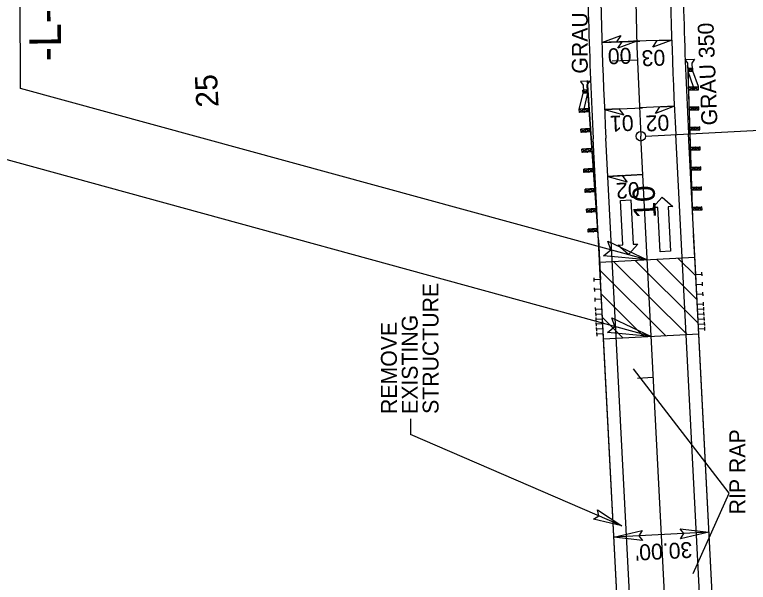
# Model space of a CAD drawing. Extents: x 1373164 to 1374172, y 550391 to 553180.
# Drawn here: x 1373510 to 1373740.9, y 551698 to 551876.6 of the extents above; entities that cross this region are included whole.
import ezdxf

# ---------------------------------------------------------------- set-up
doc = ezdxf.new("R2010")
doc.units = 0
for name, color, linetype in [('Default', 7, 'Continuous'), ('Default Symbol Cogo Elevation', 7, 'Continuous'), ('Exist Building Cogo Elevation', 7, 'Continuous'), ('Exist Building Cogo Number', 7, 'Continuous'), ('Exist Building Cogo Point CELL', 7, 'Continuous'), ('Exist Other Culture Fence Line Cogo Comment', 7, 'Continuous'), ('Exist Other Culture Fence Line Cogo Elevation', 7, 'Continuous'), ('Exist Other Culture Fence Line Cogo Point CELL', 7, 'Continuous'), ('Exist Other Culture Gate Cogo Comment', 7, 'Continuous'), ('Exist Other Culture Gate Cogo Elevation', 7, 'Continuous'), ('Exist Other Culture Gate Cogo Number', 7, 'Continuous'), ('Exist Other Culture Gate Cogo Point CELL', 7, 'Continuous'), ('Exist Roads EOP Other Cogo Elevation', 7, 'Continuous'), ('Exist Structure Major Deck Tunnel Box Culvert Cogo Point CELL', 7, 'Continuous'), ('Exist Structure Minor Pipes RCP 18 Inch Cogo Comment', 7, 'Continuous'), ('Exist Structure Minor Pipes RCP 18 Inch Cogo Elevation', 7, 'Continuous'), ('Exist Structure Minor Pipes RCP 18 Inch Cogo Number', 7, 'Continuous'), ('Exist Utilities Sanitary Sewer Manhole Cogo Elevation', 7, 'Continuous'), ('Exist Utilities Sanitary Sewer Manhole Cogo Number', 7, 'Continuous')]:
    doc.layers.add(name, color=color, linetype=linetype)

msp = doc.modelspace()

# ---------------------------------------------------------------- linework, layer by layer
at = {"layer": 'Default Symbol Cogo Elevation'}
for p, q in [((1373730.5, 551597.19), (1373718.01, 551838.94)), ((1373711.58, 551537.14), (1373696.04, 551837.8))]:
    msp.add_line(p, q, dxfattribs=at)
for radius in [1546, 1524]:
    msp.add_arc((1375239.98, 551917.59), radius, 178.33248, 182.95848, dxfattribs=at)
at = {"layer": 'Exist Building Cogo Elevation'}
for p, q in [((1373723.38, 551812.55), (1373721.87, 551861.36)), ((1373693.69, 551805.82), (1373690.24, 551855.95)), ((1373724.29, 551794.89), (1373723.65, 551807.37)), ((1373694.33, 551793.34), (1373693.69, 551805.82)), ((1373725.26, 551776.16), (1373724.29, 551794.89)), ((1373695.3, 551774.61), (1373694.33, 551793.34))]:
    msp.add_line(p, q, dxfattribs=at)
at = {"layer": 'Exist Building Cogo Number'}
for p, q in [((1373735.61, 551575.89), (1373722, 551839.14)), ((1373710.16, 551487), (1373692.04, 551837.6))]:
    msp.add_line(p, q, dxfattribs=at)
for radius in [1550, 1520]:
    msp.add_arc((1375239.98, 551917.59), radius, 180.19879, 182.95848, dxfattribs=at)
at = {"layer": 'Exist Building Cogo Point CELL'}
msp.add_line((1373710.95, 551762.41), (1373705.96, 551762.15), dxfattribs=at)
at = {"layer": 'Exist Other Culture Fence Line Cogo Comment'}
for p, q in [((1373694.05, 551798.75), (1373724.01, 551800.3)), ((1373721.59, 551775.97), (1373698.45, 551798.98)), ((1373725.08, 551779.55), (1373705.19, 551799.33)), ((1373724.7, 551786.98), (1373711.93, 551799.68)), ((1373724.32, 551794.41), (1373718.67, 551800.02)), ((1373725.26, 551776.16), (1373724.01, 551800.3)), ((1373695.3, 551774.61), (1373694.05, 551798.75)), ((1373714.85, 551775.62), (1373694.19, 551796.17)), ((1373708.11, 551775.28), (1373694.57, 551788.74)), ((1373701.37, 551774.93), (1373694.95, 551781.31))]:
    msp.add_line(p, q, dxfattribs=at)
at = {"layer": 'Exist Other Culture Fence Line Cogo Elevation'}
for p, q in [((1373695.3, 551774.61), (1373725.26, 551776.16)), ((1373731.61, 551653.33), (1373725.26, 551776.16)), ((1373701.65, 551651.78), (1373695.3, 551774.61))]:
    msp.add_line(p, q, dxfattribs=at)
at = {"layer": 'Exist Other Culture Fence Line Cogo Point CELL'}
for p, q in [((1373694.78, 551867.92), (1373706.77, 551868.31)), ((1373705.77, 551868.28), (1373694.78, 551867.92)), ((1373716.77, 551868.63), (1373704.77, 551868.25)), ((1373717.58, 551847.8), (1373706.59, 551847.29)), ((1373717.58, 551847.8), (1373706.59, 551847.29)), ((1373695.6, 551846.79), (1373707.59, 551847.34)), ((1373707.65, 551826.32), (1373696.66, 551825.75)), ((1373696.66, 551825.75), (1373707.65, 551826.32))]:
    msp.add_line(p, q, dxfattribs=at)
for points in [[(1373694.78, 551867.92), (1373700.71, 551870.12), (1373699.4, 551868.07)], [(1373705.77, 551868.28), (1373699.84, 551866.09), (1373701.15, 551868.13)], [(1373716.77, 551868.63), (1373710.83, 551866.44), (1373712.14, 551868.48)], [(1373717.58, 551847.8), (1373711.68, 551845.52), (1373712.96, 551847.59)], [(1373695.6, 551846.79), (1373701.69, 551845.07), (1373700.22, 551847)], [(1373696.66, 551825.75), (1373702.76, 551824.07), (1373701.28, 551825.99)]]:
    msp.add_lwpolyline(points, close=True, dxfattribs=at)
at = {"layer": 'Exist Other Culture Gate Cogo Comment'}
for p, q in [((1373720.95, 551862.49), (1373723.89, 551862.64)), ((1373721.87, 551861.36), (1373720.95, 551862.49)), ((1373721.97, 551859.31), (1373721.87, 551861.36)), ((1373723.89, 551862.64), (1373723.09, 551861.42)), ((1373723.09, 551861.42), (1373723.2, 551859.37)), ((1373721.88, 551859.78), (1373723.38, 551859.83)), ((1373721.88, 551859.78), (1373723.42, 551858.83)), ((1373723.38, 551812.55), (1373721.9, 551859.28)), ((1373723.38, 551859.83), (1373721.92, 551858.78)), ((1373722.58, 551859.34), (1373721.97, 551859.31)), ((1373723.2, 551859.37), (1373722.58, 551859.34)), ((1373723.42, 551858.83), (1373723.38, 551859.83)), ((1373723.42, 551858.83), (1373723.4, 551859.33)), ((1373721.92, 551858.78), (1373723.42, 551858.83)), ((1373723.6, 551853.93), (1373721.92, 551858.78)), ((1373725.13, 551853.98), (1373723.42, 551858.83)), ((1373690.95, 551855.74), (1373688.01, 551855.59)), ((1373688.01, 551855.59), (1373688.93, 551854.46)), ((1373688.93, 551854.46), (1373689.04, 551852.41)), ((1373690.15, 551854.52), (1373690.95, 551855.74)), ((1373690.26, 551852.48), (1373690.15, 551854.52)), ((1373690.31, 551852.95), (1373688.81, 551852.85)), ((1373688.88, 551851.85), (1373688.81, 551852.85)), ((1373688.81, 551852.85), (1373690.38, 551851.95)), ((1373688.88, 551851.85), (1373688.84, 551852.35)), ((1373690.31, 551852.95), (1373688.88, 551851.85)), ((1373689.04, 551852.41), (1373689.65, 551852.45)), ((1373689.65, 551852.45), (1373690.26, 551852.48)), ((1373693.69, 551805.82), (1373690.34, 551852.45)), ((1373722.07, 551853.88), (1373725.13, 551853.98)), ((1373723.63, 551852.93), (1373722.07, 551853.88)), ((1373722.1, 551852.88), (1373723.6, 551853.93)), ((1373722.1, 551852.88), (1373725.16, 551852.98)), ((1373723.63, 551852.93), (1373723.6, 551853.93)), ((1373723.6, 551853.93), (1373725.16, 551852.98)), ((1373725.13, 551853.98), (1373723.63, 551852.93)), ((1373725.16, 551852.98), (1373725.13, 551853.98)), ((1373687.67, 551846.85), (1373688.88, 551851.85)), ((1373690.38, 551851.95), (1373688.88, 551851.85)), ((1373689.2, 551846.96), (1373690.38, 551851.95)), ((1373722.27, 551847.58), (1373725.27, 551847.68)), ((1373723.8, 551846.63), (1373722.27, 551847.58)), ((1373722.3, 551846.58), (1373723.77, 551847.63)), ((1373723.8, 551846.63), (1373723.77, 551847.63)), ((1373723.77, 551847.63), (1373725.3, 551846.68)), ((1373725.27, 551847.68), (1373723.8, 551846.63)), ((1373725.3, 551846.68), (1373725.27, 551847.68)), ((1373690.73, 551847.07), (1373687.67, 551846.85)), ((1373687.74, 551845.85), (1373687.67, 551846.85)), ((1373687.67, 551846.85), (1373689.27, 551845.96)), ((1373689.2, 551846.96), (1373687.74, 551845.85)), ((1373690.8, 551846.07), (1373687.74, 551845.85)), ((1373689.27, 551845.96), (1373689.2, 551846.96)), ((1373690.8, 551846.07), (1373689.2, 551846.96)), ((1373689.27, 551845.96), (1373690.73, 551847.07)), ((1373722.3, 551846.58), (1373725.3, 551846.68)), ((1373691.18, 551840.78), (1373688.19, 551840.57)), ((1373688.26, 551839.57), (1373688.19, 551840.57)), ((1373688.19, 551840.57), (1373689.75, 551839.68)), ((1373689.68, 551840.67), (1373688.26, 551839.57)), ((1373689.75, 551839.68), (1373689.68, 551840.67)), ((1373691.25, 551839.78), (1373689.68, 551840.67)), ((1373689.75, 551839.68), (1373691.18, 551840.78)), ((1373722.47, 551841.28), (1373725.61, 551841.38)), ((1373724.07, 551840.33), (1373722.47, 551841.28)), ((1373722.5, 551840.28), (1373724.04, 551841.33)), ((1373724.07, 551840.33), (1373724.04, 551841.33)), ((1373724.04, 551841.33), (1373725.64, 551840.38)), ((1373725.61, 551841.38), (1373724.07, 551840.33)), ((1373725.64, 551840.38), (1373725.61, 551841.38)), ((1373691.25, 551839.78), (1373688.26, 551839.57)), ((1373722.5, 551840.28), (1373725.64, 551840.38)), ((1373691.63, 551834.5), (1373688.5, 551834.27)), ((1373688.57, 551833.27), (1373688.5, 551834.27)), ((1373688.5, 551834.27), (1373690.14, 551833.39)), ((1373690.07, 551834.38), (1373688.57, 551833.27)), ((1373690.14, 551833.39), (1373690.07, 551834.38)), ((1373691.7, 551833.5), (1373690.07, 551834.38)), ((1373690.14, 551833.39), (1373691.63, 551834.5)), ((1373722.67, 551834.99), (1373725.7, 551835.08)), ((1373722.7, 551833.99), (1373722.67, 551834.99)), ((1373724.22, 551834.04), (1373722.67, 551834.99)), ((1373722.7, 551833.99), (1373724.19, 551835.03)), ((1373722.7, 551833.99), (1373725.73, 551834.08)), ((1373724.22, 551834.04), (1373724.19, 551835.03)), ((1373724.19, 551835.03), (1373725.73, 551834.08)), ((1373725.7, 551835.08), (1373724.22, 551834.04)), ((1373725.73, 551834.08), (1373725.7, 551835.08)), ((1373691.7, 551833.5), (1373688.57, 551833.27)), ((1373692.08, 551828.21), (1373689.05, 551827.99)), ((1373689.12, 551827), (1373689.05, 551827.99)), ((1373689.05, 551827.99), (1373690.64, 551827.11)), ((1373690.57, 551828.1), (1373689.12, 551827)), ((1373692.15, 551827.21), (1373689.12, 551827)), ((1373690.64, 551827.11), (1373690.57, 551828.1)), ((1373692.15, 551827.21), (1373690.57, 551828.1)), ((1373690.64, 551827.11), (1373692.08, 551828.21)), ((1373692.15, 551827.21), (1373692.08, 551828.21)), ((1373722.87, 551828.69), (1373725.91, 551828.78)), ((1373724.42, 551827.74), (1373722.87, 551828.69)), ((1373722.9, 551827.69), (1373724.39, 551828.74)), ((1373722.9, 551827.69), (1373725.95, 551827.78)), ((1373724.42, 551827.74), (1373724.39, 551828.74)), ((1373724.39, 551828.74), (1373725.95, 551827.78)), ((1373725.91, 551828.78), (1373724.42, 551827.74)), ((1373725.95, 551827.78), (1373725.91, 551828.78)), ((1373723.07, 551822.39), (1373726.12, 551822.49)), ((1373724.62, 551821.44), (1373723.07, 551822.39)), ((1373723.1, 551821.39), (1373724.59, 551822.44)), ((1373724.62, 551821.44), (1373724.59, 551822.44)), ((1373724.59, 551822.44), (1373726.15, 551821.49)), ((1373726.12, 551822.49), (1373724.62, 551821.44)), ((1373726.15, 551821.49), (1373726.12, 551822.49)), ((1373692.53, 551821.93), (1373689.49, 551821.71)), ((1373689.56, 551820.71), (1373689.49, 551821.71)), ((1373689.49, 551821.71), (1373691.08, 551820.82)), ((1373691.01, 551821.82), (1373689.56, 551820.71)), ((1373692.6, 551820.93), (1373689.56, 551820.71)), ((1373691.08, 551820.82), (1373691.01, 551821.82)), ((1373692.6, 551820.93), (1373691.01, 551821.82)), ((1373691.08, 551820.82), (1373692.53, 551821.93)), ((1373723.1, 551821.39), (1373726.15, 551821.49)), ((1373692.98, 551815.64), (1373689.94, 551815.42)), ((1373690.01, 551814.43), (1373689.94, 551815.42)), ((1373689.94, 551815.42), (1373691.53, 551814.53)), ((1373691.46, 551815.53), (1373690.01, 551814.43)), ((1373691.53, 551814.53), (1373691.46, 551815.53)), ((1373693.05, 551814.64), (1373691.46, 551815.53)), ((1373691.53, 551814.53), (1373692.98, 551815.64)), ((1373723.27, 551816.09), (1373726.27, 551816.19)), ((1373723.27, 551816.09), (1373724.77, 551816.14)), ((1373723.3, 551815.09), (1373723.27, 551816.09)), ((1373724.8, 551815.14), (1373723.27, 551816.09)), ((1373724.77, 551816.14), (1373723.3, 551815.09)), ((1373723.3, 551815.09), (1373726.3, 551815.19)), ((1373724.8, 551815.14), (1373724.77, 551816.14)), ((1373724.77, 551816.14), (1373726.3, 551815.19)), ((1373726.27, 551816.19), (1373724.8, 551815.14)), ((1373726.3, 551815.19), (1373726.27, 551816.19)), ((1373693.05, 551814.64), (1373690.01, 551814.43)), ((1373693.43, 551809.36), (1373690.44, 551809.14)), ((1373690.51, 551808.14), (1373690.44, 551809.14)), ((1373690.44, 551809.14), (1373692.01, 551808.25)), ((1373691.94, 551809.25), (1373690.51, 551808.14)), ((1373693.5, 551808.36), (1373690.51, 551808.14)), ((1373693.43, 551809.36), (1373691.94, 551809.25)), ((1373692.01, 551808.25), (1373691.94, 551809.25)), ((1373691.94, 551809.25), (1373693.5, 551808.36)), ((1373692.01, 551808.25), (1373693.43, 551809.36)), ((1373693.5, 551808.36), (1373693.43, 551809.36))]:
    msp.add_line(p, q, dxfattribs=at)
at = {"layer": 'Exist Other Culture Gate Cogo Elevation'}
for p, q in [((1373724.29, 551794.89), (1373726.29, 551794.99)), ((1373725.26, 551776.16), (1373724.29, 551794.89)), ((1373726.32, 551794.42), (1373726.26, 551795.56)), ((1373692.36, 551792.66), (1373692.31, 551793.81)), ((1373694.33, 551793.34), (1373692.33, 551793.24)), ((1373695.3, 551774.61), (1373694.33, 551793.34)), ((1373726.48, 551791.3), (1373726.42, 551792.44)), ((1373692.53, 551789.54), (1373692.47, 551790.69)), ((1373694.49, 551790.22), (1373692.5, 551790.12)), ((1373724.45, 551791.77), (1373726.45, 551791.87)), ((1373692.69, 551786.42), (1373692.63, 551787.57)), ((1373724.61, 551788.65), (1373726.61, 551788.75)), ((1373726.64, 551788.18), (1373726.58, 551789.32)), ((1373694.65, 551787.1), (1373692.66, 551786.99)), ((1373724.78, 551785.53), (1373726.77, 551785.63)), ((1373726.8, 551785.06), (1373726.74, 551786.2)), ((1373692.85, 551783.3), (1373692.79, 551784.45)), ((1373694.82, 551783.98), (1373692.82, 551783.87)), ((1373692.93, 551781.74), (1373692.87, 551782.89)), ((1373724.86, 551783.96), (1373726.85, 551784.07)), ((1373726.88, 551783.5), (1373726.82, 551784.64)), ((1373726.96, 551781.94), (1373726.9, 551783.08)), ((1373694.9, 551782.42), (1373692.9, 551782.31)), ((1373693.01, 551780.18), (1373692.95, 551781.32)), ((1373694.98, 551780.86), (1373692.98, 551780.75)), ((1373724.94, 551782.4), (1373726.93, 551782.51)), ((1373725.02, 551780.84), (1373727.02, 551780.95)), ((1373727.04, 551780.38), (1373726.99, 551781.52)), ((1373693.09, 551778.62), (1373693.03, 551779.76)), ((1373695.06, 551779.3), (1373693.06, 551779.19)), ((1373693.17, 551777.06), (1373693.11, 551778.2)), ((1373725.1, 551779.28), (1373727.1, 551779.39)), ((1373727.13, 551778.81), (1373727.07, 551779.96)), ((1373727.21, 551777.25), (1373727.15, 551778.4)), ((1373695.14, 551777.74), (1373693.14, 551777.63)), ((1373693.25, 551775.5), (1373693.19, 551776.64)), ((1373695.22, 551776.17), (1373693.22, 551776.07)), ((1373725.18, 551777.72), (1373727.18, 551777.83))]:
    msp.add_line(p, q, dxfattribs=at)
at = {"layer": 'Exist Other Culture Gate Cogo Number'}
for p, q in [((1373724.29, 551794.89), (1373723.38, 551812.55)), ((1373693.69, 551805.82), (1373694.33, 551793.34))]:
    msp.add_line(p, q, dxfattribs=at)
at = {"layer": 'Exist Roads EOP Other Cogo Elevation'}
msp.add_line((1373734.13, 551313.82), (1373707.02, 551838.37), dxfattribs=at)
msp.add_arc((1375239.98, 551917.59), 1535, 171.71033, 182.95848, dxfattribs=at)
at = {"layer": 'Exist Structure Major Deck Tunnel Box Culvert Cogo Point CELL'}
for points in [[(1373696.62, 551805.32), (1373709.03, 551799.53), (1373695.3, 551800.79), (1373697.6, 551802.65)], [(1373697.87, 551781.2), (1373710.28, 551775.39), (1373696.55, 551776.66), (1373698.85, 551778.52)], [(1373693.4, 551720.77), (1373701.04, 551715.77), (1373692.1, 551717.9), (1373693.79, 551718.91)], [(1373707.59, 551711.13), (1373698.52, 551712.22), (1373707.48, 551714.28), (1373706.41, 551712.62)], [(1373719.42, 551714.85), (1373728.48, 551713.76), (1373719.53, 551711.7), (1373720.6, 551713.36)]]:
    msp.add_lwpolyline(points, close=True, dxfattribs=at)
at = {"layer": 'Exist Structure Minor Pipes RCP 18 Inch Cogo Comment'}
msp.add_line((1373705.98, 551862.28), (1373697.98, 551861.99), dxfattribs=at)
at = {"layer": 'Exist Structure Minor Pipes RCP 18 Inch Cogo Number'}
msp.add_line((1373708.52, 551838.45), (1373857.44, 551846.14), dxfattribs=at)
msp.add_circle((1373707.02, 551838.37), 1.5, dxfattribs=at)
at = {"layer": 'Exist Utilities Sanitary Sewer Manhole Cogo Elevation'}
for p, q in [((1373511.82, 551853.37), (1373511.4, 552008.55)), ((1373709.03, 551799.53), (1373511.82, 551853.37)), ((1373710.28, 551775.39), (1373461.42, 551843.6)), ((1373734.87, 551726.09), (1373704.69, 551765.2)), ((1373634.55, 551749.42), (1373634.55, 551744.57)), ((1373701.04, 551715.77), (1373634.55, 551744.57)), ((1373723.45, 551700.75), (1373734.87, 551726.09)), ((1373728.48, 551713.76), (1373698.52, 551712.22))]:
    msp.add_line(p, q, dxfattribs=at)
at = {"layer": 'Exist Utilities Sanitary Sewer Manhole Cogo Number'}
for p, q in [((1373700.61, 551818.2), (1373703.91, 551818.37)), ((1373701.33, 551804.21), (1373700.61, 551818.2)), ((1373703.91, 551818.37), (1373704.63, 551804.38)), ((1373710.85, 551815.92), (1373713.78, 551819.22)), ((1373713.78, 551819.22), (1373717.14, 551816.24)), ((1373712.35, 551815.99), (1373710.85, 551815.92)), ((1373713.07, 551802.01), (1373712.35, 551815.99)), ((1373717.14, 551816.24), (1373715.64, 551816.16)), ((1373715.64, 551816.16), (1373716.37, 551802.18)), ((1373699.84, 551804.14), (1373701.33, 551804.21)), ((1373703.2, 551801.16), (1373699.84, 551804.14)), ((1373706.13, 551804.46), (1373703.2, 551801.16)), ((1373704.63, 551804.38), (1373706.13, 551804.46)), ((1373716.37, 551802.18), (1373713.07, 551802.01))]:
    msp.add_line(p, q, dxfattribs=at)

# ---------------------------------------------------------------- texts
at = {"layer": 'Default'}
msp.add_text('RIP RAP', height=5, rotation=90.0509, dxfattribs=at).set_placement((1373739.91, 551719.4))
at = {"layer": 'Exist Other Culture Gate Cogo Comment'}
for rotation, p in [(90, (1373690.33, 551858.07)), (92.2469, (1373731.15, 551841.89))]:
    msp.add_text('GRAU 350', height=5, rotation=rotation, dxfattribs=at).set_placement(p)
at = {"layer": 'Exist Other Culture Gate Cogo Point CELL'}
for s, rotation, p in [('00', 181.8411, (1373704, 551866.24)), ('03', 181.8411, (1373714.64, 551865.63)), ('02', 182.625, (1373715.86, 551845.19)), ('01', 182.625, (1373704.64, 551845.11)), ('02', 182.9585, (1373706.53, 551824.04))]:
    msp.add_text(s, height=5, rotation=rotation, dxfattribs=at).set_placement(p)
at = {"layer": 'Exist Structure Minor Pipes RCP 18 Inch Cogo Elevation'}
for s, p in [('25', (1373574.18, 551847.64)), ('10', (1373711.86, 551812.66))]:
    msp.add_text(s, height=7, rotation=92.9585, dxfattribs=at).set_placement(p)
at = {"layer": 'Exist Structure Minor Pipes RCP 18 Inch Cogo Number'}
msp.add_text('-L- STA. 24+37.17', height=10, rotation=90.1567, dxfattribs=at).set_placement((1373524.6, 551862.03))
at = {"layer": 'Exist Utilities Sanitary Sewer Manhole Cogo Elevation'}
for s, rotation, p in [('STRUCTURE', 90.0509, (1373643.38, 551751)), ('EXISTING ', 90.0509, (1373636.83, 551750.99)), ('REMOVE ', 90.0509, (1373630.27, 551750.98)), ("30.00'", 182.9585, (1373723.1, 551710.74))]:
    msp.add_text(s, height=5, rotation=rotation, dxfattribs=at).set_placement(p)

doc.saveas('drawing.dxf')
